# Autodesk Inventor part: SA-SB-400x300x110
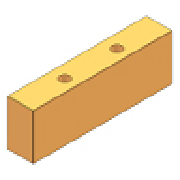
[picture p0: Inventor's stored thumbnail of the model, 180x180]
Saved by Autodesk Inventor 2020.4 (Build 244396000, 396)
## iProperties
Created: 2019-01
Part Number: SA-SB-400x300x110
Material: S 55 C
Description: Spacer Block
Document SubType Name: Modeling
Designer: mel
Standard Revision: 1
Manufacturer: FUTABA
Language: fr-FR
Size Designation: 400x300x110
Categories: <MemberInstance><Categories><Category DisplayName="Moule" InternalName="349578f2-f4d4-4954-8c09-8e99297a61c0" Mnemonic="MOLD"><Category DisplayName="Plaque de m
Density: 7.85 g/cm^3
Appearance: Orange (Pale)
IsCustomPart: 1
Author: mel
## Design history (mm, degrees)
sketch "Sketch1"
  geometry: L1 (-92, 200)-(-150, 200); L2 (-150, 200)-(-150, -200); L3 (-150, -200)-(-92, -200); L4 (-92, -200)-(-92, 200); L5 (150, 200)-(150, -200); L6 (92, -200)-(92, 200); L7 (92, 200)-(150, 200); L8 (92, -200)-(150, -200); 5 further points
  constraints: 16 end point, 3 parallel, 2 horizontal alignment, 2 midpoint, 2 perpendicular, 1 horizontal, 1 vertical
  dimensions: "d85" = 400 distance between parallel lines of L3 L1 (= L); "d86" = 58 distance between parallel lines of L4 L2 (= W_); "d88" = 58 distance between parallel lines of L5 L6 (= W_); "d89" = 150 distance from line of point (0, 0) L2 (= 0.5 x M_W); "d93" = 400 distance between parallel lines of L8 L7 (= L); "d94" = 150 distance from line of point (0, 0) L5 (= 0.5 x M_W); "d98" = 119 vertical distance of point (-120, 119) point (0, 0) (= 0.5 x S1_L); "d100" = 120 horizontal distance of point (-120, 119) point (0, 0) (= 0.5 x S1_W); "d101" = 120 horizontal distance of point (120, 119) point (0, 0) (= 0.5 x S1_W); "d102" = 119 vertical distance of point (0, 0) point (120, 119) (= 0.5 x S1_L)
extrude "Extrusion1" new body sketch "Sketch1" distance "d20" = 110 (= H_); taper "d30" = 0 deg
extrude "Extrusion2" join sketch "Sketch1" distance "d95" = 110 (= H_); taper "d96" = 0 deg
hole "Hole1" sketch "Sketch1" diameter "d129" = 16 (= S1_d1); stored, may be unused: countersink angle "d133" = 90 deg, drill point angle "d135" = 0 deg; dims "d130" = 6, "d131" = 4, "d132" = 2, "d134" = 110 (= H_)
pattern_linear "Rectangular Pattern1" dims "d156" = 119 (computed from S1_L, Ns)
hole "Hole2" sketch "Sketch1" diameter "d122" = 16 (= S1_d1); stored, may be unused: countersink angle "d126" = 90 deg, drill point angle "d128" = 0 deg; dims "d123" = 6, "d124" = 4, "d125" = 2, "d127" = 110 (= H_)
pattern_linear "Rectangular Pattern2" dims "d153" = 119 (computed from S1_L, Ns)
workplane "Work Plane1"
workplane "Work Plane2"
chamfer "Chamfer1" distance "d157" = 0.5; stored, may be unused: second distance "d158" = 2, angle "d159" = 45 deg
chamfer "Chamfer2" distance "d160" = 0.5; stored, may be unused: second distance "d161" = 2, angle "d162" = 45 deg
body "Solid1"
other parameters: "L" = 400 [user parameter; used in 2 equation terms], "W_" = 58 [user parameter; used in 2 equation terms], "H_" = 110 [user parameter; used in 5 equation terms], "S1_L" = 238 [user parameter; used in 4 equation terms], "S1_d1" = 16 [user parameter; used in 2 equation terms], "d164" = 0
